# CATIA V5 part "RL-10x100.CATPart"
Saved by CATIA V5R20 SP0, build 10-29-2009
Part number: _RL-10x100
Definition: NONE
Nomenclature: _RL-10x100
Source: Unknown
Description: PART-_RL-10x100-DESC
Bounding box of the stored display mesh (mm): x -100 to 12.5, y -6 to 6, z -6 to 6
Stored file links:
  C:\Users\Utente\Desktop\IO LAVORO\3D X SITO CF\X SITO\PLASTICA\RL\RL-10x100.CATPart
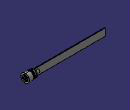
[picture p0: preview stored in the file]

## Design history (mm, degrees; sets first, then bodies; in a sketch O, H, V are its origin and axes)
Body1 "_RL-10x100" (main body)
  Solid1: solid without history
